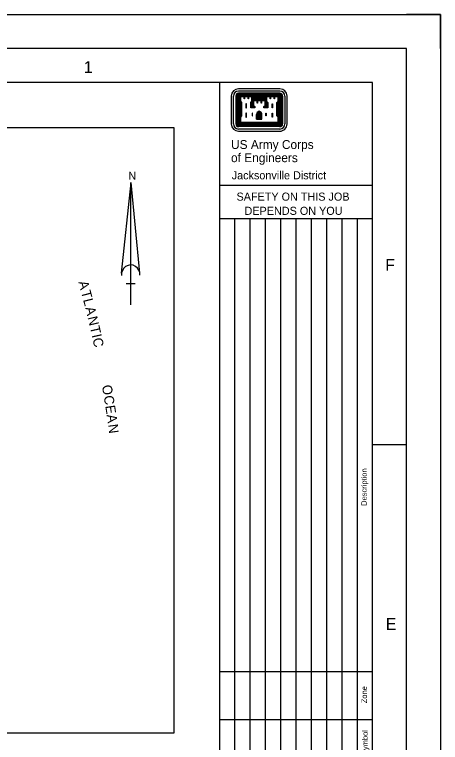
# Model space of a CAD drawing. Extents: x 384865 to 516869, y 1553900 to 1655899.
# Drawn here: x 498073 to 516865, y 1623741 to 1655899 of the extents above; entities that cross this region are included whole.
import ezdxf

# ---------------------------------------------------------------- set-up
doc = ezdxf.new("R2010")
doc.units = 0
for name, color, linetype in [('G-ANNO-NPLT', 7, 'Continuous'), ('G-ANNO-TEXT-LOGO', 7, 'Continuous'), ('G-ANNO-TEXT-TTLB', 7, 'Continuous'), ('G-ANNO-TTLB', 7, 'Continuous'), ('V-ANNO-SYMB', 7, 'Continuous')]:
    doc.layers.add(name, color=color, linetype=linetype)

msp = doc.modelspace()

# ---------------------------------------------------------------- linework, layer by layer
at = {"layer": 'G-ANNO-NPLT'}
msp.add_lwpolyline([(384865, 1655899), (516865, 1655899), (516865, 1553900), (384865, 1553900)], close=True, dxfattribs=at)
msp.add_lwpolyline([(516865, 1654399), (516865, 1655899), (515365, 1655899)], dxfattribs=at)
at = {"layer": 'G-ANNO-TEXT-LOGO'}
for p, q in [((509780, 1652618), (507957, 1652618)), ((507957, 1652522), (509780, 1652522)), ((509780, 1652420), (507957, 1652420)), ((509780, 1652393), (507957, 1652393)), ((509780, 1652366), (507957, 1652366)), ((509780, 1652342), (507957, 1652342)), ((509780, 1652315), (507957, 1652315)), ((507636, 1652297), (507636, 1651067)), ((507732, 1651067), (507732, 1652297)), ((507837, 1652297), (507837, 1651067)), ((507864, 1652297), (507864, 1651067)), ((507888, 1652297), (507888, 1651067)), ((507915, 1652297), (507915, 1651067)), ((507942, 1652297), (507942, 1651067)), ((507969, 1652297), (507969, 1651076)), ((507993, 1652297), (507993, 1651103)), ((508014, 1652036), (508014, 1651406)), ((508041, 1652009), (508041, 1651436)), ((508590, 1652291), (509148, 1652291)), ((508590, 1652264), (509148, 1652264)), ((508590, 1652240), (509148, 1652240)), ((508590, 1652213), (509148, 1652213)), ((508590, 1652186), (509148, 1652186)), ((508590, 1652162), (509148, 1652162)), ((508590, 1652135), (509148, 1652135)), ((509696, 1652009), (509696, 1651436)), ((509723, 1652033), (509723, 1651409)), ((509744, 1652297), (509744, 1651103)), ((509768, 1652297), (509768, 1651076)), ((509795, 1652297), (509795, 1651067)), ((509822, 1652297), (509822, 1651067)), ((509846, 1652297), (509846, 1651067)), ((509873, 1652297), (509873, 1651067)), ((509900, 1652297), (509900, 1651067)), ((510002, 1652297), (510002, 1651067)), ((510101, 1651067), (510101, 1652297)), ((508749, 1651280), (508749, 1651481)), ((508773, 1651280), (508773, 1651481)), ((508800, 1651280), (508800, 1651481)), ((508827, 1651280), (508827, 1651481)), ((508851, 1651280), (508851, 1651481)), ((508887, 1651280), (508887, 1651481)), ((508911, 1651280), (508911, 1651481)), ((508938, 1651280), (508938, 1651481)), ((508965, 1651280), (508965, 1651481)), ((508989, 1651280), (508989, 1651481)), ((509780, 1651049), (507957, 1651049)), ((509780, 1651025), (507957, 1651025)), ((509768, 1651076), (507969, 1651076)), ((509744, 1651103), (507993, 1651103)), ((508749, 1651280), (508989, 1651280)), ((509780, 1650998), (507957, 1650998)), ((509780, 1650971), (507957, 1650971)), ((509780, 1650947), (507957, 1650947)), ((509780, 1650842), (507957, 1650842)), ((507957, 1650743), (509780, 1650743))]:
    msp.add_line(p, q, dxfattribs=at)
for points in [[(508014, 1652297), (508014, 1652060), (508065, 1652009), (508065, 1651436), (508014, 1651382), (508014, 1651121), (509723, 1651121), (509723, 1651382), (509669, 1651436), (509669, 1652009), (509723, 1652060), (509723, 1652297), (509498, 1652297), (509324, 1652297), (509163, 1652297), (509163, 1652060), (509220, 1652009), (509220, 1651799), (509094, 1651799), (509094, 1651820), (509148, 1651874), (509148, 1652108), (508923, 1652108), (508749, 1652108), (508590, 1652108), (508590, 1651874), (508644, 1651820), (508644, 1651799), (508518, 1651799), (508518, 1652009), (508572, 1652060), (508572, 1652297), (508347, 1652297), (508173, 1652297), (508014, 1652297)], [(508038, 1652270), (508038, 1652072), (508092, 1652018), (508092, 1651424), (508038, 1651370), (508038, 1651148), (509699, 1651148), (509699, 1651370), (509642, 1651424), (509642, 1652018), (509699, 1652072), (509699, 1652270), (509537, 1652270), (509537, 1652177), (509522, 1652177), (509522, 1652270), (509363, 1652270), (509363, 1652177), (509351, 1652177), (509351, 1652270), (509190, 1652270), (509190, 1652072), (509244, 1652018), (509244, 1651775), (509070, 1651775), (509070, 1651832), (509124, 1651886), (509124, 1652084), (508962, 1652084), (508962, 1651991), (508950, 1651991), (508950, 1652084), (508788, 1652084), (508788, 1651991), (508773, 1651991), (508773, 1652084), (508614, 1652084), (508614, 1651886), (508668, 1651832), (508668, 1651775), (508494, 1651775), (508494, 1652018), (508548, 1652072), (508548, 1652270), (508389, 1652270), (508389, 1652177), (508374, 1652177), (508374, 1652270), (508212, 1652270), (508212, 1652177), (508200, 1652177), (508200, 1652270), (508038, 1652270)], [(508560, 1652012), (508545, 1651997), (508545, 1651826), (508602, 1651826), (508563, 1651865), (508563, 1652015)], [(509178, 1652012), (509193, 1651997), (509193, 1651826), (509139, 1651826), (509175, 1651865), (509175, 1652015)], [(508284, 1651949), (508284, 1651775), (508302, 1651775), (508302, 1651949), (508284, 1651949)], [(509450, 1651949), (509450, 1651775), (509435, 1651775), (509435, 1651949), (509450, 1651949)], [(508284, 1651550), (508284, 1651373), (508302, 1651373), (508302, 1651550), (508284, 1651550)], [(508560, 1651550), (508560, 1651427), (508575, 1651427), (508575, 1651550), (508560, 1651550)], [(509178, 1651550), (509178, 1651427), (509163, 1651427), (509163, 1651550), (509178, 1651550)], [(509450, 1651550), (509450, 1651373), (509435, 1651373), (509435, 1651550), (509450, 1651550)]]:
    msp.add_lwpolyline(points, dxfattribs=at)
for centre, major_axis, start_param, end_param in [((507957, 1652297), (321, 0), 1.57078, 3.141576), ((507957, 1652297), (225, 0), 1.57078, 3.141576), ((507957, 1652297), (121, 0), 1.57078, 3.141576), ((507957, 1652297), (94.5, 0), 1.57078, 3.141576), ((507957, 1652297), (68.4, 0), 1.57078, 3.141576), ((507957, 1652297), (42.4, 0), 1.57078, 3.141576), ((507957, 1652297), (16.4, 0), 1.57078, 3.141576), ((509779, 1652297), (321, 0), 6.283169, 7.853965), ((509779, 1652297), (225, 0), 6.28317, 7.853966), ((509779, 1652297), (121, 0), 6.283169, 7.853965), ((509779, 1652297), (94.5, 0), 6.283169, 7.853965), ((509779, 1652297), (68.4, 0), 6.283169, 7.853965), ((509779, 1652297), (42.4, 0), 6.283169, 7.853965), ((509779, 1652297), (16.4, 0), 6.283169, 7.853965), ((508913, 1651467), (-167, 0), 4.985832, 6.214359), ((508913, 1651467), (-141, 0), 4.947465, 6.21436), ((508913, 1651467), (-115, 0), 4.947465, 6.21436), ((508913, 1651467), (-88.5, 0), 4.947465, 6.21436), ((508823, 1651467), (62.4, 0), 0.068794, 1.335689), ((508823, 1651467), (88.5, 0), 0.068794, 1.335689), ((508823, 1651467), (115, 0), 0.068795, 1.335689), ((508913, 1651467), (-62.4, 0), 4.947465, 6.214359), ((508823, 1651467), (141, 0), 0.068795, 1.335689), ((508823, 1651467), (167, 0), 0.068795, 1.29842), ((507957, 1651066), (-321, 0), 6.28317, 7.853966), ((507957, 1651066), (-225, 0), 6.28317, 7.853966), ((507957, 1651066), (-121, 0), 6.28317, 7.853966), ((507957, 1651066), (-94.5, 0), 6.28317, 7.853966), ((507957, 1651066), (-68.4, 0), 6.28317, 7.853966), ((507957, 1651066), (-42.4, 0), 6.28317, 7.853966), ((507957, 1651066), (-16.4, 0), 6.28317, 7.853966), ((509779, 1651066), (121, 0), 4.712373, 6.28317), ((509779, 1651066), (94.5, 0), 4.712373, 6.28317), ((509779, 1651066), (68.4, 0), 4.712373, 6.28317), ((509779, 1651066), (42.4, 0), 4.712373, 6.28317), ((509779, 1651066), (16.4, 0), 4.712373, 6.28317), ((509779, 1651066), (321, 0), 4.712373, 6.28317), ((509779, 1651066), (-225, 0), 1.570781, 3.141577)]:
    msp.add_ellipse(centre, major_axis=major_axis, ratio=0.99964, start_param=start_param, end_param=end_param, dxfattribs=at)
at = {"layer": 'G-ANNO-TTLB'}
for p, q in [((507114, 1652899), (507114, 1556900)), ((507115, 1648362), (513865, 1648362)), ((507096, 1646889), (513846, 1646889)), ((507784, 1646889), (507784, 1621751)), ((508459, 1646889), (508459, 1621751)), ((509134, 1646889), (509134, 1621751)), ((509809, 1646889), (509809, 1621751)), ((510484, 1646889), (510484, 1621751)), ((511159, 1646889), (511159, 1621751)), ((511834, 1646889), (511834, 1621751)), ((512509, 1646889), (512509, 1621751)), ((513184, 1646889), (513184, 1621751)), ((515365, 1636894), (513865, 1636894)), ((507115, 1626882), (513865, 1626882)), ((507115, 1624747), (513865, 1624747))]:
    msp.add_line(p, q, dxfattribs=at)
for points in [[(386365, 1555400), (515365, 1555400), (515365, 1654399), (386365, 1654399)], [(513865, 1652899), (390115, 1652899), (390115, 1556900), (513865, 1556900)]]:
    msp.add_lwpolyline(points, close=True, dxfattribs=at)
at = {"layer": 'V-ANNO-SYMB'}
for p, q in [((505114, 1650899), (475479, 1650899)), ((505114, 1624160), (505114, 1650899)), ((502796, 1644472), (503213, 1648479)), ((503199, 1643080), (503199, 1648480)), ((503602, 1644470), (503211, 1648481)), ((502995, 1644011), (503400, 1644011)), ((475479, 1624160), (505114, 1624160))]:
    msp.add_line(p, q, dxfattribs=at)
msp.add_arc((503199, 1644430), 405, 353.3459, 188.7908, dxfattribs=at)

# ---------------------------------------------------------------- texts
at = {"layer": 'G-ANNO-TEXT-TTLB'}
for s, height, p in [('US Army Corps', 392.58, (507624, 1649960)), ('of Engineers', 392.58, (507624, 1649378)), ('Jacksonville District', 356.99, (507654, 1648619)), ('SAFETY ON THIS JOB', 357, (507867, 1647677)), ('DEPENDS ON YOU', 357, (508221, 1647050))]:
    msp.add_text(s, height=height, dxfattribs=at).set_placement(p)
for s, p in [('Description', (513613, 1634193)), ('Zone', (513622, 1625472)), ('Symbol', (513657, 1623182))]:
    msp.add_text(s, height=240, rotation=90, dxfattribs=at).set_placement(p)
at = {"layer": 'G-ANNO-TTLB'}
for s, p in [('1', (501127, 1653315)), ('F', (514428, 1644580)), ('E', (514452, 1628714))]:
    msp.add_text(s, height=525, dxfattribs=at).set_placement(p)
at = {"layer": 'V-ANNO-SYMB'}
for s, height, rotation, p in [('N', 354, 0, (503097, 1648599)), ('A', 432, 285.3188, (500884, 1644077)), ('T', 432, 284.8034, (500999, 1643656)), ('L', 432, 284.3674, (501094, 1643300)), ('A', 432, 283.9315, (501186, 1642942)), ('N', 432, 283.4161, (501291, 1642519)), ('T', 432, 282.9008, (501392, 1642095)), ('I', 432, 282.4648, (501474, 1641736)), ('C', 432, 282.2667, (501511, 1641572)), ('O', 432, 279.7701, (501924, 1639501)), ('C', 432, 279.215, (502003, 1639038)), ('E', 432, 278.6996, (502073, 1638608)), ('A', 432, 278.2236, (502134, 1638210)), ('N', 432, 277.7082, (502197, 1637779))]:
    msp.add_text(s, height=height, rotation=rotation, dxfattribs=at).set_placement(p)

doc.saveas('drawing.dxf')
